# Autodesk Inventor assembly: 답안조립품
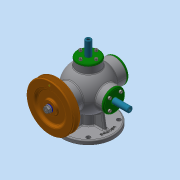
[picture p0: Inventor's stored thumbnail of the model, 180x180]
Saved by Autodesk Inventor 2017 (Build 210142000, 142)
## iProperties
Part Number: 답안조립품
Material: 일반
Document SubType Name: Assembly
Designer: MRC
Author: MRC
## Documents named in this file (17)
- C:\Users\MRC\Desktop\600911V1003\답안조립품.iam
- C:\Users\MRC\Desktop\600911V1003\본체.ipt
- C:\Users\MRC\Desktop\600911V1003\V-벨트풀리.ipt
- C:\Users\MRC\Desktop\600911V1003\너트 M8x1.ipt
- C:\Users\MRC\Desktop\600911V1003\뒤커버.ipt
- C:\Users\MRC\Desktop\600911V1003\베어링 6202.ipt
- C:\Users\MRC\Desktop\600911V1003\본체커버.ipt
- C:\Users\MRC\Desktop\600911V1003\볼트 M4.ipt
- C:\Users\MRC\Desktop\600911V1003\스프링1.ipt
- C:\Users\MRC\Desktop\600911V1003\스프링2.ipt
- C:\Users\MRC\Desktop\600911V1003\슬라이드 커버.ipt
- C:\Users\MRC\Desktop\600911V1003\슬라이드.ipt
- C:\Users\MRC\Desktop\600911V1003\앞커버.ipt
- C:\Users\MRC\Desktop\600911V1003\오일 실.ipt
- C:\Users\MRC\Desktop\600911V1003\와셔 8x17.ipt
- C:\Users\MRC\Desktop\600911V1003\축.ipt
- C:\Users\MRC\Desktop\600911V1003\키 4x4.ipt
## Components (1 placed, 1 different names)
1. V-벨트풀리:1
